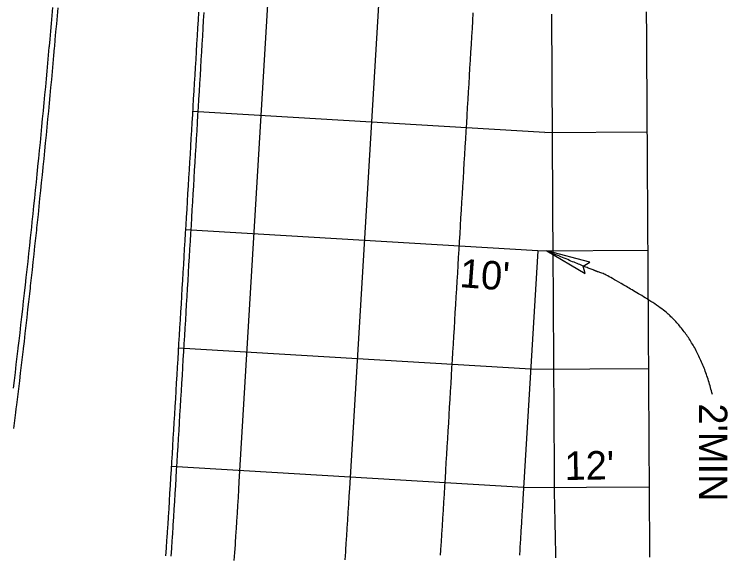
# Model space of a CAD drawing. Extents: x 2145147 to 2158018, y 137519 to 148068.
# Drawn here: x 2150687.4 to 2150777.7, y 144635.2 to 144703.6 of the extents above; entities that cross this region are included whole.
import ezdxf

# ---------------------------------------------------------------- set-up
doc = ezdxf.new("R2010")
doc.units = 0
for name, color, linetype in [('PR_Dimensions', 7, 'Continuous'), ('PR_Joint_Contraction', 7, 'Continuous'), ('PR_Joint_Long', 7, 'Continuous'), ('PR_Phasing_Pavement_1', 7, 'Continuous'), ('PR_Road_Concrete', 7, 'Continuous')]:
    doc.layers.add(name, color=color, linetype=linetype)

msp = doc.modelspace()

# ---------------------------------------------------------------- linework, layer by layer
at = {"layer": 'PR_Dimensions'}
msp.add_lwpolyline([(2150754.793, 144673.644), (2150759.628, 144670.79), (2150759.387, 144671.705), (2150760.216, 144672.206)], close=True, dxfattribs=at)
msp.add_open_spline([(2150775.738, 144655.491), (2150773.693, 144663.778), (2150762.242, 144670.746), (2150761.087, 144670.988), (2150754.793, 144673.644)], degree=2, dxfattribs=at)
at = {"layer": 'PR_Joint_Contraction'}
for p, q in [((2150754.558, 144688.61), (2150709.972, 144691.286)), ((2150754.558, 144688.61), (2150767.51, 144688.688)), ((2150753.659, 144673.637), (2150709.073, 144676.313)), ((2150753.659, 144673.637), (2150767.6, 144673.721)), ((2150752.761, 144658.664), (2150708.174, 144661.34)), ((2150752.761, 144658.664), (2150767.69, 144658.754)), ((2150751.862, 144643.691), (2150707.275, 144646.367)), ((2150751.862, 144643.691), (2150767.78, 144643.786))]:
    msp.add_line(p, q, dxfattribs=at)
at = {"layer": 'PR_Joint_Long'}
for points in [[(2150750.328, 145218.945), (2150715.84, 144644.411), (2150715.782, 144643.442), (2150715.721, 144642.445), (2150715.659, 144641.448), (2150715.597, 144640.452), (2150715.534, 144639.455), (2150715.47, 144638.458), (2150715.449, 144638.132), (2150715.406, 144637.462), (2150715.365, 144636.833), (2150715.341, 144636.466), (2150715.275, 144635.469), (2150715.209, 144634.473)], [(2150751.472, 145004.362), (2150729.815, 144643.57), (2150729.756, 144642.593), (2150729.694, 144641.587), (2150729.632, 144640.581), (2150729.569, 144639.574), (2150729.506, 144638.568), (2150729.442, 144637.563), (2150729.42, 144637.231), (2150729.377, 144636.555), (2150729.335, 144635.921), (2150729.311, 144635.548), (2150729.245, 144634.543)], [(2150745.45, 144703.771), (2150745.39, 144702.773), (2150745.33, 144701.775), (2150745.27, 144700.777), (2150745.211, 144699.778), (2150745.151, 144698.78), (2150745.091, 144697.782), (2150745.031, 144696.784), (2150744.971, 144695.786), (2150744.911, 144694.787), (2150744.851, 144693.789), (2150744.791, 144692.791), (2150744.731, 144691.793), (2150744.671, 144690.795), (2150744.611, 144689.796), (2150744.551, 144688.798), (2150744.491, 144687.8), (2150744.432, 144686.802), (2150744.372, 144685.804), (2150744.312, 144684.805), (2150744.252, 144683.807), (2150744.192, 144682.809), (2150744.132, 144681.811), (2150744.072, 144680.812), (2150744.012, 144679.814), (2150743.952, 144678.816), (2150743.892, 144677.818), (2150743.832, 144676.82), (2150743.772, 144675.821), (2150743.713, 144674.823), (2150743.653, 144673.825), (2150743.593, 144672.827), (2150743.533, 144671.829), (2150743.473, 144670.83), (2150743.413, 144669.832), (2150743.353, 144668.834), (2150743.293, 144667.836), (2150743.233, 144666.838), (2150743.173, 144665.839), (2150743.113, 144664.841), (2150743.053, 144663.843), (2150742.994, 144662.845), (2150742.934, 144661.847), (2150742.874, 144660.848), (2150742.814, 144659.85), (2150742.754, 144658.852), (2150742.694, 144657.854), (2150742.634, 144656.856), (2150742.574, 144655.857), (2150742.514, 144654.859), (2150742.454, 144653.861), (2150742.394, 144652.863), (2150742.334, 144651.865), (2150742.274, 144650.866), (2150742.215, 144649.868), (2150742.155, 144648.87), (2150742.095, 144647.872), (2150742.035, 144646.874), (2150741.975, 144645.875), (2150741.915, 144644.877), (2150741.855, 144643.879), (2150741.795, 144642.881), (2150741.793, 144642.853), (2150741.734, 144641.866), (2150741.672, 144640.851), (2150741.609, 144639.837), (2150741.546, 144638.822), (2150741.482, 144637.807), (2150741.417, 144636.792), (2150741.396, 144636.46), (2150741.351, 144635.778), (2150741.31, 144635.138)], [(2150755.945, 144634.828), (2150755.925, 144635.828), (2150755.904, 144636.827), (2150755.884, 144637.827), (2150755.864, 144638.827), (2150755.844, 144639.827), (2150755.823, 144640.827), (2150755.803, 144641.827), (2150755.786, 144642.667), (2150755.785, 144642.827), (2150755.779, 144643.827), (2150755.778, 144644.066), (2150755.773, 144644.827), (2150755.767, 144645.827), (2150755.761, 144646.827), (2150755.755, 144647.827), (2150755.749, 144648.827), (2150755.743, 144649.827), (2150755.737, 144650.827), (2150755.731, 144651.827), (2150755.725, 144652.827), (2150755.719, 144653.827), (2150755.713, 144654.827), (2150755.707, 144655.827), (2150755.701, 144656.827), (2150755.695, 144657.827), (2150755.689, 144658.827), (2150755.683, 144659.827), (2150755.677, 144660.827), (2150755.671, 144661.827), (2150755.665, 144662.827), (2150755.659, 144663.827), (2150755.653, 144664.826), (2150755.647, 144665.826), (2150755.641, 144666.826), (2150755.635, 144667.826), (2150755.629, 144668.826), (2150755.623, 144669.826), (2150755.617, 144670.826), (2150755.611, 144671.826), (2150755.609, 144672.095), (2150755.42, 144703.583)], [(2150767.833, 144634.899), (2150767.827, 144635.899), (2150767.821, 144636.899), (2150767.815, 144637.899), (2150767.809, 144638.899), (2150767.803, 144639.899), (2150767.797, 144640.899), (2150767.791, 144641.899), (2150767.786, 144642.739), (2150767.785, 144642.899), (2150767.779, 144643.899), (2150767.777, 144644.138), (2150767.773, 144644.899), (2150767.767, 144645.899), (2150767.761, 144646.899), (2150767.755, 144647.899), (2150767.749, 144648.899), (2150767.743, 144649.899), (2150767.737, 144650.899), (2150767.731, 144651.899), (2150767.725, 144652.899), (2150767.719, 144653.899), (2150767.713, 144654.899), (2150767.707, 144655.899), (2150767.701, 144656.899), (2150767.695, 144657.899), (2150767.689, 144658.899), (2150767.683, 144659.899), (2150767.677, 144660.899), (2150767.671, 144661.899), (2150767.665, 144662.899), (2150767.659, 144663.899), (2150767.653, 144664.899), (2150767.647, 144665.899), (2150767.641, 144666.899), (2150767.635, 144667.899), (2150767.629, 144668.899), (2150767.623, 144669.898), (2150767.617, 144670.898), (2150767.611, 144671.898), (2150767.609, 144672.167), (2150767.605, 144672.898), (2150767.599, 144673.898), (2150767.593, 144674.898), (2150767.587, 144675.898), (2150767.581, 144676.898), (2150767.575, 144677.898), (2150767.569, 144678.898), (2150767.563, 144679.898), (2150767.557, 144680.898), (2150767.551, 144681.898), (2150767.545, 144682.898), (2150767.539, 144683.898), (2150767.533, 144684.898), (2150767.527, 144685.898), (2150767.521, 144686.898), (2150767.515, 144687.898), (2150767.509, 144688.898), (2150767.503, 144689.898), (2150767.497, 144690.898), (2150767.491, 144691.898), (2150767.485, 144692.898), (2150767.479, 144693.898), (2150767.473, 144694.898), (2150767.466, 144695.898), (2150767.46, 144696.898), (2150767.454, 144697.898), (2150767.448, 144698.898), (2150767.442, 144699.898), (2150767.436, 144700.898), (2150767.43, 144701.898), (2150767.424, 144702.898), (2150767.418, 144703.898)], [(2150753.659, 144673.637), (2150751.775, 144642.252), (2150751.716, 144641.26), (2150751.653, 144640.239), (2150751.59, 144639.217), (2150751.526, 144638.195), (2150751.462, 144637.173), (2150751.396, 144636.153), (2150751.375, 144635.816), (2150751.33, 144635.13)]]:
    msp.add_lwpolyline(points, dxfattribs=at)
at = {"layer": 'PR_Phasing_Pavement_1'}
for points in [[(2150687.31, 144656.265), (2150687.431, 144657.266), (2150687.55, 144658.268), (2150687.669, 144659.271), (2150687.787, 144660.273), (2150687.904, 144661.275), (2150687.915, 144661.37), (2150688.021, 144662.277), (2150688.137, 144663.28), (2150688.252, 144664.282), (2150688.367, 144665.285), (2150688.481, 144666.287), (2150688.594, 144667.29), (2150688.706, 144668.293), (2150688.785, 144668.998), (2150688.818, 144669.296), (2150688.929, 144670.299), (2150689.039, 144671.302), (2150689.149, 144672.305), (2150689.258, 144673.308), (2150689.366, 144674.311), (2150689.474, 144675.315), (2150689.581, 144676.318), (2150689.614, 144676.63), (2150689.687, 144677.321), (2150689.792, 144678.325), (2150689.897, 144679.329), (2150690.001, 144680.332), (2150690.105, 144681.336), (2150690.207, 144682.34), (2150690.309, 144683.344), (2150690.402, 144684.267), (2150690.41, 144684.348), (2150690.511, 144685.352), (2150690.611, 144686.356), (2150690.71, 144687.36), (2150690.808, 144688.364), (2150690.906, 144689.369), (2150691.003, 144690.373), (2150691.1, 144691.378), (2150691.15, 144691.908), (2150691.195, 144692.382), (2150691.29, 144693.387), (2150691.384, 144694.392), (2150691.478, 144695.396), (2150691.571, 144696.401), (2150691.663, 144697.406), (2150691.754, 144698.411), (2150691.845, 144699.416), (2150691.857, 144699.553), (2150691.935, 144700.421), (2150692.025, 144701.426), (2150692.113, 144702.431), (2150692.2, 144703.426), (2150692.201, 144703.436), (2150692.288, 144704.442)], [(2150687.362, 144651.174), (2150687.485, 144652.176), (2150687.608, 144653.178), (2150687.668, 144653.665), (2150687.731, 144654.18), (2150687.852, 144655.183), (2150687.973, 144656.185), (2150688.093, 144657.187), (2150688.213, 144658.19), (2150688.332, 144659.192), (2150688.45, 144660.195), (2150688.567, 144661.197), (2150688.578, 144661.292), (2150688.684, 144662.2), (2150688.8, 144663.203), (2150688.915, 144664.206), (2150689.03, 144665.209), (2150689.144, 144666.212), (2150689.257, 144667.215), (2150689.37, 144668.219), (2150689.448, 144668.924), (2150689.481, 144669.222), (2150689.593, 144670.225), (2150689.703, 144671.229), (2150689.813, 144672.232), (2150689.922, 144673.236), (2150690.03, 144674.24), (2150690.138, 144675.244), (2150690.245, 144676.247), (2150690.278, 144676.56), (2150690.351, 144677.251), (2150690.456, 144678.255), (2150690.561, 144679.26), (2150690.665, 144680.264), (2150690.769, 144681.268), (2150690.871, 144682.272), (2150690.973, 144683.277), (2150691.067, 144684.2), (2150691.075, 144684.281), (2150691.175, 144685.286), (2150691.275, 144686.29), (2150691.374, 144687.295), (2150691.473, 144688.3), (2150691.571, 144689.304), (2150691.668, 144690.309), (2150691.764, 144691.314), (2150691.815, 144691.845), (2150691.86, 144692.319), (2150691.955, 144693.324), (2150692.049, 144694.329), (2150692.143, 144695.335), (2150692.236, 144696.34), (2150692.328, 144697.345), (2150692.419, 144698.351), (2150692.51, 144699.356), (2150692.522, 144699.493), (2150692.6, 144700.362), (2150692.69, 144701.367), (2150692.778, 144702.373), (2150692.865, 144703.368), (2150692.866, 144703.379), (2150692.954, 144704.384)]]:
    msp.add_lwpolyline(points, dxfattribs=at)
at = {"layer": 'PR_Road_Concrete'}
for points in [[(2150710.726, 144703.852), (2150710.666, 144702.854), (2150710.606, 144701.856), (2150710.546, 144700.857), (2150710.486, 144699.859), (2150710.426, 144698.861), (2150710.366, 144697.863), (2150710.307, 144696.865), (2150710.247, 144695.866), (2150710.187, 144694.868), (2150710.127, 144693.87), (2150710.067, 144692.872), (2150710.007, 144691.874), (2150709.947, 144690.875), (2150709.887, 144689.877), (2150709.827, 144688.879), (2150709.767, 144687.881), (2150709.707, 144686.883), (2150709.647, 144685.884), (2150709.588, 144684.886), (2150709.528, 144683.888), (2150709.468, 144682.89), (2150709.408, 144681.891), (2150709.348, 144680.893), (2150709.288, 144679.895), (2150709.228, 144678.897), (2150709.168, 144677.899), (2150709.108, 144676.9), (2150709.048, 144675.902), (2150708.988, 144674.904), (2150708.928, 144673.906), (2150708.868, 144672.908), (2150708.809, 144671.909), (2150708.749, 144670.911), (2150708.689, 144669.913), (2150708.629, 144668.915), (2150708.569, 144667.917), (2150708.509, 144666.918), (2150708.449, 144665.92), (2150708.389, 144664.922), (2150708.329, 144663.924), (2150708.269, 144662.926), (2150708.209, 144661.927), (2150708.149, 144660.929), (2150708.09, 144659.931), (2150708.03, 144658.933), (2150707.97, 144657.935), (2150707.91, 144656.936), (2150707.85, 144655.938), (2150707.79, 144654.94), (2150707.73, 144653.942), (2150707.67, 144652.944), (2150707.61, 144651.945), (2150707.55, 144650.947), (2150707.49, 144649.949), (2150707.43, 144648.951), (2150707.37, 144647.953), (2150707.311, 144646.954), (2150707.251, 144645.956), (2150707.191, 144644.958), (2150707.189, 144644.93), (2150707.131, 144643.967), (2150707.07, 144642.976), (2150707.009, 144641.986), (2150706.947, 144640.995), (2150706.885, 144640.004), (2150706.822, 144639.014), (2150706.801, 144638.689), (2150706.758, 144638.023), (2150706.717, 144637.399), (2150706.693, 144637.033), (2150706.628, 144636.043), (2150706.562, 144635.052)], [(2150711.391, 144703.812), (2150711.332, 144702.814), (2150711.272, 144701.816), (2150711.212, 144700.817), (2150711.152, 144699.819), (2150711.092, 144698.821), (2150711.032, 144697.823), (2150710.972, 144696.825), (2150710.912, 144695.826), (2150710.852, 144694.828), (2150710.792, 144693.83), (2150710.732, 144692.832), (2150710.672, 144691.834), (2150710.612, 144690.835), (2150710.553, 144689.837), (2150710.493, 144688.839), (2150710.433, 144687.841), (2150710.373, 144686.843), (2150710.313, 144685.844), (2150710.253, 144684.846), (2150710.193, 144683.848), (2150710.133, 144682.85), (2150710.073, 144681.852), (2150710.013, 144680.853), (2150709.953, 144679.855), (2150709.893, 144678.857), (2150709.834, 144677.859), (2150709.774, 144676.861), (2150709.714, 144675.862), (2150709.654, 144674.864), (2150709.594, 144673.866), (2150709.534, 144672.868), (2150709.474, 144671.87), (2150709.414, 144670.871), (2150709.354, 144669.873), (2150709.294, 144668.875), (2150709.234, 144667.877), (2150709.174, 144666.879), (2150709.115, 144665.88), (2150709.055, 144664.882), (2150708.995, 144663.884), (2150708.935, 144662.886), (2150708.875, 144661.887), (2150708.815, 144660.889), (2150708.755, 144659.891), (2150708.695, 144658.893), (2150708.635, 144657.895), (2150708.575, 144656.896), (2150708.515, 144655.898), (2150708.455, 144654.9), (2150708.395, 144653.902), (2150708.336, 144652.904), (2150708.276, 144651.905), (2150708.216, 144650.907), (2150708.156, 144649.909), (2150708.096, 144648.911), (2150708.036, 144647.913), (2150707.976, 144646.914), (2150707.916, 144645.916), (2150707.856, 144644.918), (2150707.855, 144644.89), (2150707.796, 144643.927), (2150707.736, 144642.935), (2150707.675, 144641.944), (2150707.613, 144640.953), (2150707.55, 144639.962), (2150707.487, 144638.971), (2150707.466, 144638.646), (2150707.423, 144637.98), (2150707.382, 144637.355), (2150707.358, 144636.989), (2150707.293, 144635.998), (2150707.227, 144635.008)]]:
    msp.add_lwpolyline(points, dxfattribs=at)

# ---------------------------------------------------------------- texts
at = {"layer": 'PR_Dimensions'}
for s, rotation, p in [("10'", 355.66722, (2150743.675, 144669.073)), ("2'MIN", 269.99961, (2150774.032, 144654.353)), ("12'", 0.81931, (2150757.064, 144644.655))]:
    msp.add_text(s, height=3.6, rotation=rotation, dxfattribs=at).set_placement(p)

doc.saveas('drawing.dxf')
